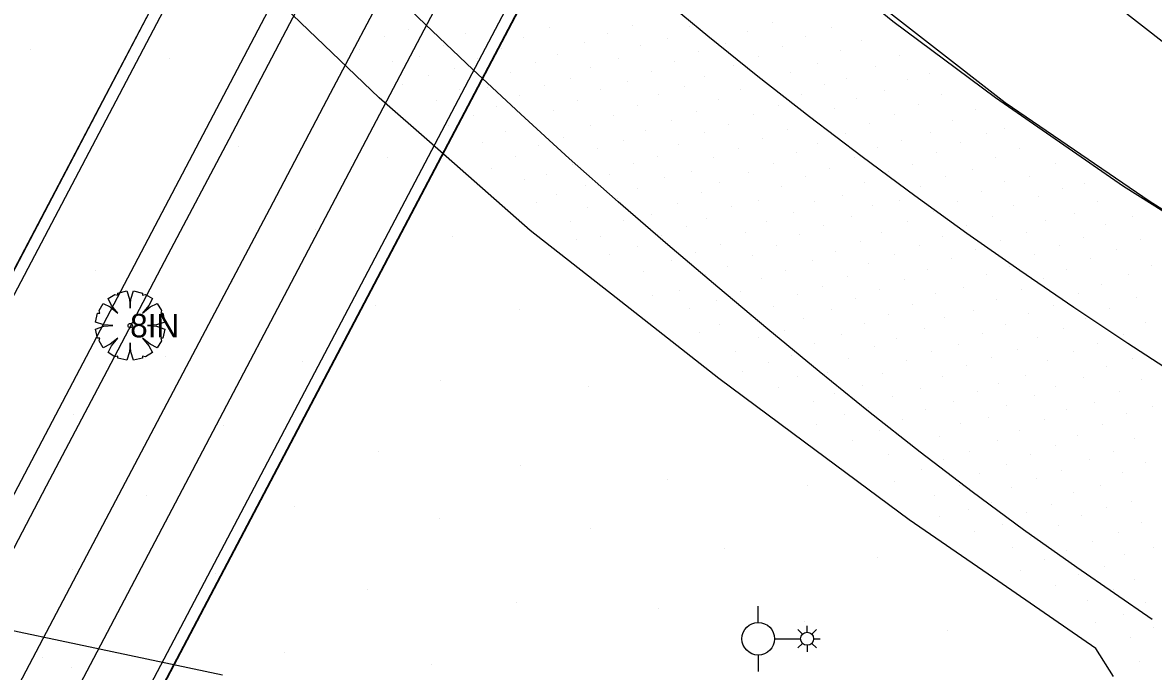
# Model space of a CAD drawing. Extents: x 1732346 to 1733076, y 467730 to 468633.
# Drawn here: x 1732739.5 to 1732826.1, y 468090 to 468139.6 of the extents above; entities that cross this region are included whole.
import ezdxf

# ---------------------------------------------------------------- set-up
doc = ezdxf.new("R2010")
doc.units = 0
for name, color, linetype in [('Default', 7, 'Continuous'), ('S_Bridge_BoxCulvert', 7, 'Continuous'), ('S_Ground_SpotElevation', 7, 'Continuous'), ('S_Guardrail_Beam', 7, 'Continuous'), ('S_Railroad_Tracks', 7, 'Continuous'), ('S_Roadway_Edge_Pavement', 7, 'Continuous'), ('S_Roadway_Painted_Lines', 7, 'Continuous'), ('S_Text', 7, 'Continuous'), ('S_Trees_Bush_Line', 7, 'Continuous'), ('S_Trees_Decid_NonPay', 7, 'Continuous'), ('S_Utilities_Pole_StreetLight', 7, 'Continuous'), ('TopoDOT Temp', 7, 'Continuous')]:
    doc.layers.add(name, color=color, linetype=linetype)

# ---------------------------------------------------------------- blocks, each defined once
blk = doc.blocks.new('POINT_DISPLAY')
at = {"layer": 'Default'}
blk.add_line((0, 0), (0, 0), dxfattribs=at)

msp = doc.modelspace()

# ---------------------------------------------------------------- linework, layer by layer
at = {"layer": 'S_Bridge_BoxCulvert'}
for p, q in [((1732639.349, 467931.595), (1732772.729, 468185.159)), ((1732639.356, 467931.621), (1732772.736, 468185.185)), ((1732640.157, 467931.201), (1732773.537, 468184.766)), ((1732646.436, 467927.898), (1732779.815, 468181.463)), ((1732656.397, 467922.658), (1732789.777, 468176.223)), ((1732660.637, 467920.428), (1732794.017, 468173.993)), ((1732661.386, 467920.002), (1732794.766, 468173.567)), ((1732661.436, 467920.006), (1732794.816, 468173.571))]:
    msp.add_line(p, q, dxfattribs=at)
at = {"layer": 'S_Guardrail_Beam'}
msp.add_lwpolyline([(1732784.382, 468159.331), (1732785.099, 468158.378), (1732792.825, 468151.4), (1732802.762, 468142.865), (1732814.72, 468133.514), (1732825.815, 468125.941), (1732836.325, 468119.351), (1732849.385, 468111.474), (1732864.593, 468102.997), (1732885.992, 468092.153), (1732906.222, 468082.865), (1732922.81, 468075.745), (1732936.425, 468070.374), (1732944.226, 468067.605), (1732958.088, 468062.882), (1732972.686, 468058.256), (1732988.331, 468053.793), (1732995.824, 468051.775), (1733007.391, 468048.851), (1733017.284, 468046.625), (1733034.703, 468042.774), (1733054.044, 468038.708), (1733073.975, 468034.234)], dxfattribs=at)
at = {"layer": 'S_Railroad_Tracks'}
for points in [[(1732794.809, 468194.505), (1732790.156, 468185.654), (1732786.365, 468178.442), (1732781.701, 468169.596), (1732777.038, 468160.75), (1732772.374, 468151.904), (1732767.711, 468143.058), (1732763.047, 468134.212), (1732758.384, 468125.366), (1732753.721, 468116.52), (1732749.057, 468107.674), (1732744.394, 468098.828), (1732739.73, 468089.982), (1732735.067, 468081.136), (1732730.403, 468072.29), (1732725.74, 468063.444), (1732721.076, 468054.598), (1732716.413, 468045.752), (1732711.749, 468036.906), (1732707.086, 468028.06), (1732702.422, 468019.214), (1732697.759, 468010.368), (1732693.095, 468001.522), (1732688.432, 467992.676)], [(1732680.786, 467989.136), (1732685.443, 467997.986), (1732690.1, 468006.835), (1732694.757, 468015.685), (1732699.414, 468024.534), (1732704.07, 468033.384), (1732708.727, 468042.233), (1732713.384, 468051.083), (1732718.041, 468059.932), (1732722.698, 468068.782), (1732727.355, 468077.631), (1732732.012, 468086.481), (1732736.669, 468095.33), (1732741.325, 468104.18), (1732745.982, 468113.029), (1732750.639, 468121.879), (1732755.296, 468130.728), (1732759.953, 468139.578), (1732764.61, 468148.427), (1732769.267, 468157.277), (1732773.924, 468166.126), (1732778.581, 468174.976), (1732783.237, 468183.825), (1732787.789, 468192.475)]]:
    msp.add_lwpolyline(points, dxfattribs=at)
at = {"layer": 'S_Roadway_Edge_Pavement'}
for points in [[(1732823.007, 468089.57), (1732821.659, 468091.736), (1732813.423, 468097.407), (1732807.383, 468101.566), (1732799.356, 468107.529), (1732792.806, 468112.395), (1732784.933, 468118.56), (1732778.351, 468123.714), (1732770.846, 468130.322), (1732766.796, 468133.889), (1732759.562, 468140.794), (1732752.667, 468147.374), (1732745.846, 468154.686), (1732740.622, 468160.287), (1732734.263, 468168.005), (1732729.679, 468173.568), (1732723.729, 468181.605), (1732721.39, 468184.764), (1732715.912, 468193.131)], [(1732837.239, 468118.646), (1732823.774, 468127.095), (1732813.991, 468133.891), (1732806.132, 468139.717), (1732798.824, 468145.7), (1732788.591, 468154.667)], [(1732677.839, 468105.951), (1732687.624, 468103.887), (1732697.408, 468101.822), (1732707.193, 468099.758), (1732716.978, 468097.693), (1732726.762, 468095.629), (1732736.547, 468093.564), (1732745.022, 468091.776), (1732754.805, 468089.704)]]:
    msp.add_lwpolyline(points, dxfattribs=at)
at = {"layer": 'S_Roadway_Painted_Lines'}
for points in [[(1732825.966, 468093.946), (1732820.204, 468097.932), (1732816.137, 468100.822), (1732812.193, 468103.722), (1732808.216, 468106.752), (1732804.26, 468109.866), (1732800.477, 468112.919), (1732796.559, 468116.159), (1732792.712, 468119.384), (1732788.887, 468122.626), (1732785.092, 468125.927), (1732781.349, 468129.243), (1732777.649, 468132.626), (1732773.968, 468136.047), (1732770.341, 468139.484), (1732766.734, 468142.956), (1732763.187, 468146.439), (1732759.62, 468149.983), (1732756.116, 468153.527), (1732752.639, 468157.117), (1732749.224, 468160.76), (1732745.832, 468164.467), (1732742.496, 468168.204), (1732739.21, 468171.965)], [(1732828.314, 468112.333), (1732824.121, 468115.073), (1732819.975, 468117.834), (1732815.858, 468120.67), (1732811.793, 468123.502), (1732807.801, 468126.378), (1732803.774, 468129.36), (1732799.739, 468132.424), (1732795.797, 468135.502), (1732791.946, 468138.611), (1732788.116, 468141.801)]]:
    msp.add_lwpolyline(points, dxfattribs=at)
at = {"layer": 'S_Trees_Bush_Line'}
msp.add_lwpolyline([(1733076.457, 468046.745), (1733041.715, 468052.429), (1733015.862, 468057.837), (1732966.818, 468070.303), (1732920.395, 468084.59), (1732889.536, 468097.751), (1732857.392, 468112.01), (1732836.107, 468130.901), (1732810.433, 468150.929), (1732778.494, 468176.218), (1732763.066, 468193.027), (1732750.601, 468208.657)], dxfattribs=at)
at = {"layer": 'S_Trees_Decid_NonPay'}
msp.add_lwpolyline([(1732746.402, 468116.444), (1732745.713, 468116.497), (1732745.076, 468116.709), (1732745.235, 468117.399), (1732745.394, 468117.399), (1732745.341, 468117.611), (1732745.659, 468118.141), (1732746.189, 468117.876), (1732746.774, 468117.399), (1732746.296, 468117.982), (1732746.031, 468118.513), (1732746.561, 468118.831), (1732746.774, 468118.778), (1732746.774, 468118.937), (1732747.463, 468119.096), (1732747.675, 468118.46), (1732747.728, 468117.77), (1732747.781, 468118.46), (1732747.993, 468119.096), (1732748.683, 468118.937), (1732748.683, 468118.778), (1732748.895, 468118.831), (1732749.426, 468118.513), (1732749.16, 468117.982), (1732748.683, 468117.399), (1732749.266, 468117.876), (1732749.796, 468118.141), (1732750.115, 468117.611), (1732750.062, 468117.399), (1732750.221, 468117.399), (1732750.381, 468116.709), (1732749.744, 468116.497), (1732749.054, 468116.444), (1732749.744, 468116.391), (1732750.381, 468116.179), (1732750.221, 468115.489), (1732750.062, 468115.489), (1732750.115, 468115.277), (1732749.796, 468114.747), (1732749.266, 468115.012), (1732748.683, 468115.489), (1732749.16, 468114.906), (1732749.426, 468114.375), (1732748.895, 468114.057), (1732748.683, 468114.11), (1732748.683, 468113.951), (1732747.993, 468113.792), (1732747.781, 468114.428), (1732747.728, 468115.118), (1732747.675, 468114.428), (1732747.463, 468113.792), (1732746.774, 468113.951), (1732746.774, 468114.11), (1732746.561, 468114.057), (1732746.031, 468114.375), (1732746.296, 468114.906), (1732746.774, 468115.489), (1732746.189, 468115.012), (1732745.659, 468114.747), (1732745.341, 468115.277), (1732745.394, 468115.489), (1732745.235, 468115.489), (1732745.076, 468116.179), (1732745.713, 468116.391), (1732746.402, 468116.444)], dxfattribs=at)
msp.add_circle((1732747.728, 468116.444), 0.166, dxfattribs=at)
at = {"layer": 'S_Utilities_Pole_StreetLight'}
for p, q in [((1732795.817, 468093.718), (1732795.817, 468094.965)), ((1732799.56, 468092.969), (1732799.56, 468093.468)), ((1732797.065, 468092.47), (1732799.061, 468092.47)), ((1732799.207, 468092.823), (1732798.854, 468093.176)), ((1732799.912, 468092.823), (1732800.265, 468093.176)), ((1732800.059, 468092.47), (1732800.558, 468092.47)), ((1732799.207, 468092.117), (1732798.854, 468091.764)), ((1732799.56, 468091.971), (1732799.56, 468091.472)), ((1732799.912, 468092.117), (1732800.265, 468091.764)), ((1732795.817, 468091.222), (1732795.817, 468089.975))]:
    msp.add_line(p, q, dxfattribs=at)
for centre, radius in [((1732795.817, 468092.47), 1.248), ((1732799.56, 468092.47), 0.499)]:
    msp.add_circle(centre, radius, dxfattribs=at)
at = {"layer": 'TopoDOT Temp'}
for p, q in [((1732759.953, 468139.578), (1732759.953, 468139.578)), ((1732763.047, 468134.212), (1732763.047, 468134.212)), ((1732755.296, 468130.728), (1732755.296, 468130.728)), ((1732758.384, 468125.366), (1732758.384, 468125.366)), ((1732750.639, 468121.879), (1732750.639, 468121.879)), ((1732753.721, 468116.52), (1732753.721, 468116.52)), ((1732745.982, 468113.029), (1732745.982, 468113.029)), ((1732749.057, 468107.674), (1732749.057, 468107.674)), ((1732741.325, 468104.18), (1732741.325, 468104.18)), ((1732744.394, 468098.828), (1732744.394, 468098.828)), ((1732739.73, 468089.982), (1732739.73, 468089.982))]:
    msp.add_line(p, q, dxfattribs=at)

# ---------------------------------------------------------------- block references
at = {"layer": 'S_Ground_SpotElevation'}
for p in [(1732769.019, 468139.13), (1732779.808, 468139.277), (1732786.204, 468139.45), (1732790.52, 468139.362), (1732796.944, 468139.634), (1732801.396, 468139.26), (1732767.219, 468138.542), (1732773.375, 468138.843), (1732777.875, 468138.511), (1732784.3, 468138.837), (1732788.891, 468138.4), (1732794.97, 468138.992), (1732799.461, 468138.6), (1732803.697, 468138.251), (1732740.08, 468137.543), (1732765.292, 468137.606), (1732771.746, 468137.876), (1732776.171, 468137.657), (1732782.478, 468138.113), (1732786.812, 468137.87), (1732791.276, 468137.461), (1732793.302, 468138.023), (1732797.668, 468137.838), (1732802.109, 468137.472), (1732750.753, 468136.868), (1732767.787, 468136.631), (1732769.898, 468137.034), (1732774.287, 468136.883), (1732778.752, 468136.605), (1732780.471, 468137.182), (1732785.09, 468136.886), (1732789.382, 468136.665), (1732795.835, 468137.069), (1732806.594, 468137.092), (1732772.553, 468136.126), (1732776.884, 468135.843), (1732782.955, 468136.169), (1732787.678, 468135.929), (1732793.903, 468136.384), (1732798.313, 468135.785), (1732800.331, 468136.499), (1732804.76, 468136.3), (1732808.917, 468135.758), (1732768.58, 468134.878), (1732770.563, 468135.573), (1732779.463, 468134.852), (1732781.422, 468135.339), (1732785.842, 468135.138), (1732791.687, 468135.543), (1732796.511, 468134.936), (1732800.899, 468134.91), (1732802.587, 468135.382), (1732807.24, 468135.249), (1732772.97, 468134.488), (1732775.053, 468134.683), (1732777.525, 468134.025), (1732783.76, 468134.511), (1732788.157, 468134.113), (1732790.192, 468134.735), (1732794.48, 468134.492), (1732799.127, 468134.135), (1732805.506, 468134.452), (1732809.842, 468134.152), (1732771.199, 468133.682), (1732775.799, 468133.224), (1732781.942, 468133.683), (1732786.556, 468133.322), (1732792.773, 468133.741), (1732797.359, 468133.328), (1732803.355, 468133.799), (1732808.111, 468133.338), (1732773.977, 468132.552), (1732778.05, 468132.206), (1732780.172, 468132.911), (1732784.761, 468132.536), (1732791.1, 468132.813), (1732795.47, 468132.617), (1732799.885, 468132.261), (1732801.688, 468133.027), (1732806.212, 468132.609), (1732812.452, 468132.992), (1732744.918, 468132.073), (1732772.062, 468131.799), (1732782.939, 468131.729), (1732787.176, 468131.386), (1732789.14, 468132.173), (1732793.536, 468131.839), (1732798.065, 468131.478), (1732804.347, 468131.896), (1732810.706, 468132.171), (1732814.644, 468131.558), (1732774.669, 468130.448), (1732776.483, 468131.272), (1732780.893, 468130.821), (1732785.506, 468130.618), (1732791.663, 468131.189), (1732796.171, 468130.744), (1732802.474, 468131.165), (1732806.767, 468130.636), (1732808.968, 468131.23), (1732813.317, 468131.116), (1732756.038, 468130.19), (1732779.012, 468130.246), (1732783.543, 468130.025), (1732789.744, 468130.275), (1732794.339, 468130.025), (1732798.733, 468129.688), (1732800.347, 468130.422), (1732804.959, 468130.086), (1732809.467, 468129.701), (1732811.316, 468130.444), (1732815.782, 468130.038), (1732767.435, 468129.298), (1732777.21, 468129.379), (1732781.597, 468128.741), (1732786.258, 468128.832), (1732788.131, 468129.352), (1732792.41, 468129.276), (1732796.954, 468128.865), (1732803.152, 468129.34), (1732807.599, 468128.771), (1732813.991, 468129.288), (1732818.556, 468128.861), (1732775.357, 468128.492), (1732779.631, 468128.046), (1732784.416, 468128.016), (1732790.718, 468128.26), (1732795.034, 468128.139), (1732799.46, 468127.849), (1732801.255, 468128.456), (1732805.805, 468128.21), (1732812.237, 468128.414), (1732777.927, 468127.622), (1732782.556, 468127.182), (1732788.656, 468127.788), (1732792.828, 468127.39), (1732797.635, 468127.098), (1732803.972, 468127.399), (1732808.23, 468127.087), (1732810.128, 468127.837), (1732814.689, 468127.483), (1732816.569, 468127.841), (1732820.778, 468127.291), (1732780.368, 468126.485), (1732785.056, 468126.205), (1732786.556, 468126.966), (1732791.444, 468126.631), (1732802.274, 468126.412), (1732812.895, 468126.722), (1732817.287, 468126.327), (1732819.116, 468126.951), (1732778.84, 468125.831), (1732782.745, 468125.465), (1732789.607, 468125.806), (1732793.799, 468125.557), (1732795.822, 468126.039), (1732800.145, 468125.979), (1732804.549, 468125.614), (1732806.612, 468126.034), (1732811.065, 468125.953), (1732815.385, 468125.656), (1732821.823, 468125.97), (1732750.083, 468125.212), (1732781.444, 468124.428), (1732785.516, 468124.483), (1732787.633, 468124.945), (1732791.859, 468124.612), (1732796.441, 468124.433), (1732798.491, 468125.137), (1732802.959, 468124.776), (1732807.264, 468124.439), (1732809.226, 468125.158), (1732813.719, 468124.785), (1732817.777, 468124.487), (1732820.042, 468125.018), (1732824.491, 468124.822), (1732761.913, 468123.773), (1732790.292, 468124.043), (1732794.832, 468123.582), (1732800.829, 468124.095), (1732805.257, 468123.593), (1732811.793, 468124.085), (1732816.341, 468123.556), (1732822.415, 468124.193), (1732772.435, 468123.257), (1732781.889, 468123.017), (1732783.761, 468123.256), (1732788.429, 468123.317), (1732799.01, 468123.4), (1732803.617, 468122.871), (1732809.957, 468123.264), (1732814.338, 468122.978), (1732820.742, 468123.177), (1732825.068, 468123.018), (1732784.391, 468121.871), (1732786.557, 468122.489), (1732791.027, 468122.018), (1732792.893, 468122.65), (1732795.352, 468121.817), (1732797.177, 468122.598), (1732801.702, 468122.145), (1732806.212, 468121.874), (1732808.135, 468122.594), (1732812.464, 468122.274), (1732816.975, 468121.858), (1732818.873, 468122.597), (1732823.263, 468122.295), (1732789.176, 468121.415), (1732793.474, 468120.957), (1732799.967, 468121.465), (1732804.253, 468121.163), (1732810.58, 468121.56), (1732815.09, 468120.968), (1732821.233, 468121.566), (1732825.945, 468121.056), (1732745.059, 468120.637), (1732787.061, 468120.552), (1732791.749, 468120.381), (1732796.035, 468120.056), (1732797.92, 468120.698), (1732802.649, 468120.183), (1732808.809, 468120.747), (1732813.292, 468120.358), (1732819.408, 468120.744), (1732824.145, 468120.321), (1732755.575, 468119.814), (1732800.761, 468119.447), (1732805.096, 468119.212), (1732807.031, 468119.97), (1732811.505, 468119.355), (1732815.97, 468119.233), (1732817.647, 468120.037), (1732822.082, 468119.597), (1732787.737, 468118.771), (1732789.765, 468119.16), (1732792.604, 468118.376), (1732794.477, 468119.079), (1732798.839, 468118.859), (1732803.251, 468118.524), (1732809.376, 468118.891), (1732814.077, 468118.423), (1732820.35, 468118.929), (1732824.773, 468118.584), (1732766.492, 468118.001), (1732777.554, 468117.66), (1732790.558, 468117.779), (1732796.949, 468117.921), (1732801.412, 468117.67), (1732807.601, 468118.029), (1732812.269, 468117.623), (1732818.442, 468117.969), (1732822.689, 468117.782), (1732795.251, 468117.154), (1732799.311, 468116.981), (1732803.924, 468116.624), (1732805.771, 468117.331), (1732810.1, 468117.094), (1732816.536, 468117.373), (1732820.883, 468116.958), (1732825.467, 468116.709), (1732791.321, 468115.925), (1732792.816, 468116.541), (1732797.826, 468116.069), (1732802.22, 468115.801), (1732808.532, 468116.211), (1732813.021, 468115.833), (1732814.759, 468116.56), (1732819.178, 468116.219), (1732823.816, 468115.793), (1732795.868, 468115.529), (1732800.114, 468115.084), (1732806.4, 468115.49), (1732811.168, 468114.98), (1732817.212, 468115.547), (1732821.8, 468115.076), (1732750.408, 468114.112), (1732794.053, 468114.464), (1732798.339, 468114.187), (1732804.721, 468114.832), (1732809.1, 468114.424), (1732815.647, 468114.639), (1732819.938, 468114.457), (1732760.887, 468113.714), (1732796.582, 468113.627), (1732802.717, 468113.931), (1732807.19, 468113.769), (1732811.751, 468113.372), (1732813.655, 468113.972), (1732817.961, 468113.783), (1732822.469, 468113.282), (1732824.473, 468113.903), (1732771.52, 468112.269), (1732794.644, 468112.919), (1732798.793, 468112.522), (1732801.089, 468112.886), (1732805.346, 468112.809), (1732809.904, 468112.524), (1732816.265, 468112.619), (1732820.727, 468112.48), (1732825.136, 468112.286), (1732782.821, 468111.748), (1732797.394, 468111.68), (1732803.775, 468111.85), (1732808.225, 468111.594), (1732812.597, 468111.41), (1732814.205, 468112.032), (1732818.591, 468111.778), (1732800.044, 468110.6), (1732801.622, 468111.28), (1732806.084, 468111.046), (1732810.742, 468110.629), (1732816.998, 468111.118), (1732821.6, 468110.595), (1732823.439, 468111.397), (1732804.286, 468110.183), (1732808.613, 468110.054), (1732814.84, 468110.346), (1732819.425, 468110.016), (1732824.018, 468109.678), (1732826.017, 468110.256), (1732743.404, 468109.615), (1732754.842, 468108.805), (1732800.3, 468108.836), (1732802.455, 468109.618), (1732806.863, 468109.267), (1732811.276, 468108.921), (1732813.424, 468109.433), (1732817.717, 468109.241), (1732822.164, 468108.866), (1732805.063, 468108.4), (1732809.72, 468107.986), (1732815.803, 468108.377), (1732820.292, 468108.066), (1732803.064, 468107.627), (1732807.487, 468107.375), (1732814.143, 468107.673), (1732818.582, 468107.293), (1732824.619, 468107.821), (1732766.772, 468106.809), (1732805.76, 468106.55), (1732810.033, 468106.204), (1732812.018, 468106.842), (1732816.694, 468106.603), (1732821.21, 468106.214), (1732823.032, 468106.803), (1732777.608, 468105.723), (1732808.352, 468105.391), (1732814.794, 468105.826), (1732825.451, 468105.987), (1732788.884, 468104.644), (1732806.225, 468104.496), (1732812.784, 468105.147), (1732817.134, 468104.706), (1732819.046, 468105.332), (1732823.706, 468105.195), (1732799.606, 468104.183), (1732811.221, 468104.175), (1732815.22, 468104.062), (1732819.991, 468103.665), (1732822.009, 468104.18), (1732748.973, 468103.474), (1732809.297, 468103.448), (1732813.68, 468102.87), (1732824.38, 468102.971), (1732760.271, 468102.581), (1732811.929, 468102.368), (1732816.373, 468102.129), (1732818.285, 468102.732), (1732820.535, 468101.884), (1732822.469, 468102.487), (1732771.382, 468101.683), (1732809.703, 468101.806), (1732814.55, 468101.216), (1732818.787, 468101.113), (1732825.171, 468101.387), (1732782.984, 468100.893), (1732812.406, 468100.706), (1732816.65, 468100.254), (1732823.413, 468100.592), (1732793.223, 468099.373), (1732815.26, 468099.482), (1732821.394, 468099.908), (1732826.055, 468099.492), (1732804.934, 468098.68), (1732817.709, 468098.503), (1732819.432, 468099.263), (1732823.83, 468098.887), (1732743.3, 468097.739), (1732815.927, 468097.691), (1732822.308, 468098), (1732754.236, 468097.448), (1732820.359, 468097.358), (1732824.64, 468097.001), (1732765.879, 468096.248), (1732818.587, 468096.547), (1732823.025, 468096.211), (1732777.31, 468095.259), (1732821.064, 468095.4), (1732825.48, 468095.213), (1732788.167, 468094.801), (1732823.801, 468094.296), (1732799.379, 468093.826), (1732821.624, 468093.696), (1732826.063, 468093.35), (1732810.318, 468093.071), (1732824.301, 468092.536), (1732741.037, 468091.071), (1732759.521, 468091.387), (1732824.992, 468090.715), (1732743.253, 468090.257), (1732770.761, 468090.533)]:
    msp.add_blockref('POINT_DISPLAY', p, dxfattribs=at)

# ---------------------------------------------------------------- texts
at = {"layer": 'S_Text'}
msp.add_text('8IN', height=1.8, dxfattribs=at).set_placement((1732747.728, 468115.544))

doc.saveas('drawing.dxf')
